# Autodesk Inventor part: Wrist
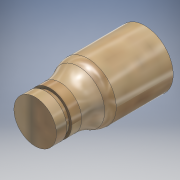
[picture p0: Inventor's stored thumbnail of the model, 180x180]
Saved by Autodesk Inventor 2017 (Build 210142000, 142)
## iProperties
Created: 2017-06
Part Number: Wrist
Material: Generic
Document SubType Name: Modeling
Designer: alez_
Density: 1 g/cm^3
Appearance: Natural Maple - Glossy Dark Tint
Author: alez_
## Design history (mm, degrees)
sketch "Sketch1"
  geometry: C1 r 11.25 at (0, 0); 1 further point
  constraints: 1 centre point, 1 coincident
  dimensions: "d0" = 22.5 diameter of C1
extrude "Extrusion1" new body sketch "Sketch1" distance "d1" = 5.5; taper "d2" = 0 deg
sketch "Sketch2"
  geometry: C1 r 10 at (0, 0); 1 further point
  constraints: 1 centre point, 1 coincident
  dimensions: "d3" = 20 diameter of C1
extrude "Extrusion2" join sketch "Sketch2" distance "d4" = 2.5; taper "d5" = 0 deg
sketch "Sketch3"
  geometry: C1 r 11.25 at (0, 0); 1 further point
  constraints: 1 centre point, 1 coincident
extrude "Extrusion3" join sketch "Sketch3" distance "d6" = 50; taper "d7" = 0 deg
sketch "Sketch4"
  geometry: C1 r 11.25 at (0, 0) reference; C2 r 15 at (0, 0); 1 further point
  constraints: 1 centre point, 1 coincident
  dimensions: "d8" = 30 diameter of C2
extrude "Extrusion4" join sketch "Sketch4" distance "d9" = 33; taper "d10" = 0 deg
fillet "Fillet1" dims "d11" = 20
fillet "Fillet2" dims "d12" = 10
sketch "Sketch5"
  geometry: C1 r 12.5 at (0, 0); 1 further point
  constraints: 1 centre point, 1 coincident
  dimensions: "d13" = 25 diameter of C1
extrude "Extrusion5" cut sketch "Sketch5" distance "d14" = 33; taper "d15" = 0 deg
sketch "Sketch6"
  geometry: C1 r 8.75 at (0, 0); 1 further point
  constraints: 1 centre point, 1 coincident
  dimensions: "d16" = 17.5 diameter of C1
extrude "Extrusion6" cut sketch "Sketch6" distance "d17" = 12.75; taper "d18" = 0 deg
fillet "Fillet3" dims "d19" = 20
body "Solid1"
